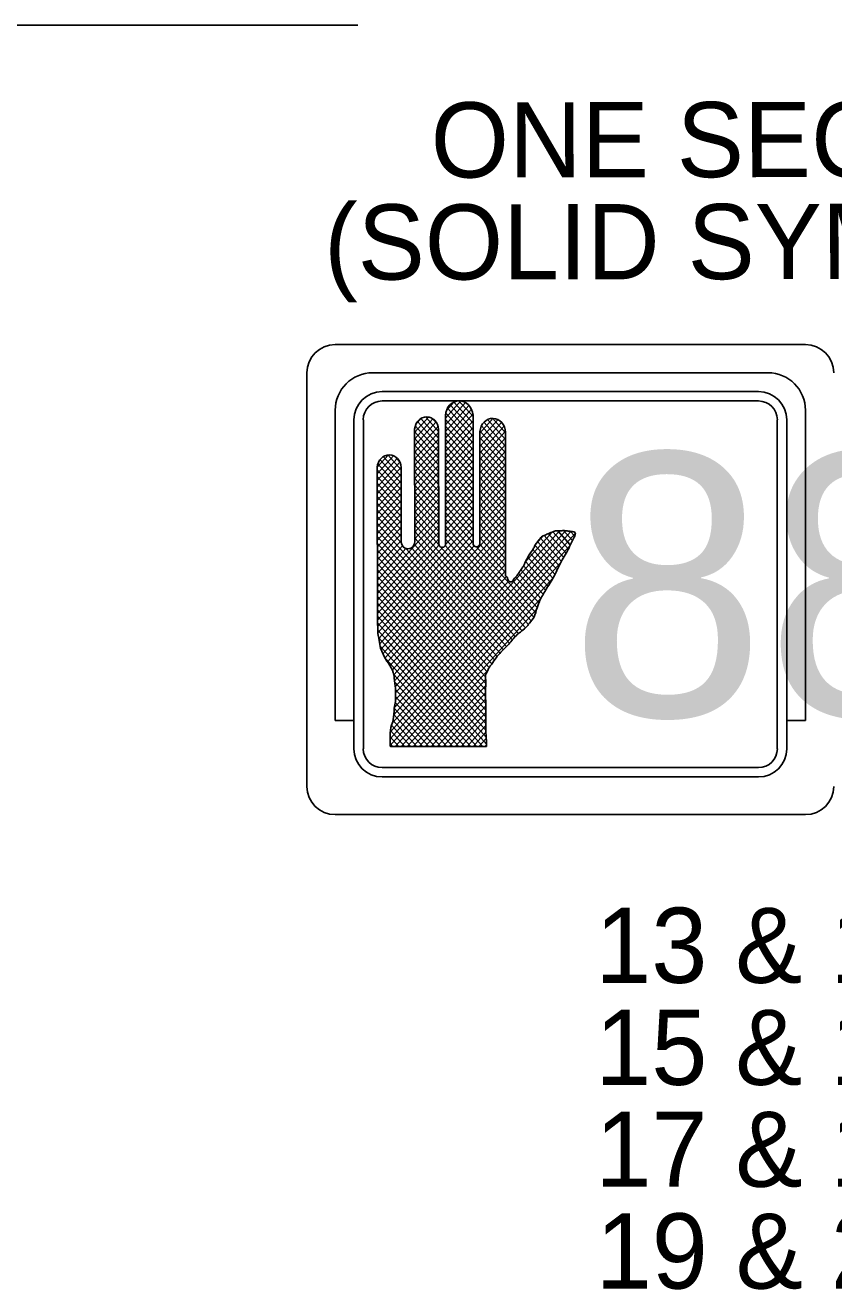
# Model space of a CAD drawing. Extents: x 1 to 35.4, y 0.4 to 10.6.
# Drawn here: x 4.903 to 5.619, y 9.065 to 10.185 of the extents above; entities that cross this region are included whole.
import ezdxf

# ---------------------------------------------------------------- set-up
doc = ezdxf.new("R2010")
doc.units = 0
doc.layers.add('T_Drafting', color=7, linetype='Continuous')
doc.layers.add('T_Notes', color=7, linetype='Continuous')

msp = doc.modelspace()

# ---------------------------------------------------------------- linework, layer by layer
at = {"layer": 'T_Drafting'}
for p, q in [((5.1772, 9.9023), (5.5938, 9.9023)), ((5.1522, 9.8773), (5.1522, 9.5106)), ((5.2105, 9.8773), (5.5605, 9.8773)), ((5.2188, 9.8606), (5.5522, 9.8606)), ((5.2188, 9.8523), (5.5522, 9.8523)), ((5.2749, 9.837), (5.2886, 9.8523)), ((5.2867, 9.8524), (5.2993, 9.8384)), ((5.1772, 9.844), (5.1772, 9.569)), ((5.2749, 9.8312), (5.2927, 9.8509)), ((5.2749, 9.8253), (5.2957, 9.8484)), ((5.2749, 9.8194), (5.298, 9.845)), ((5.2749, 9.8135), (5.2992, 9.8405)), ((5.2751, 9.8416), (5.2993, 9.8148)), ((5.2758, 9.8439), (5.2825, 9.8514)), ((5.2767, 9.8458), (5.2993, 9.8207)), ((5.2791, 9.849), (5.2993, 9.8266)), ((5.2823, 9.8513), (5.2993, 9.8325)), ((5.2945, 9.8496), (5.2968, 9.847)), ((5.5938, 9.569), (5.5938, 9.844)), ((5.1938, 9.8356), (5.1938, 9.544)), ((5.2022, 9.8356), (5.2022, 9.544)), ((5.2476, 9.8244), (5.2599, 9.838)), ((5.2476, 9.8185), (5.2637, 9.8364)), ((5.2476, 9.8126), (5.2666, 9.8337)), ((5.2476, 9.8067), (5.2684, 9.8298)), ((5.2482, 9.8303), (5.2688, 9.8074)), ((5.2485, 9.8313), (5.2537, 9.8371)), ((5.2501, 9.8341), (5.2688, 9.8133)), ((5.253, 9.8367), (5.2688, 9.8192)), ((5.2571, 9.8381), (5.2688, 9.8251)), ((5.2642, 9.8361), (5.267, 9.833)), ((5.275, 9.7256), (5.2749, 9.8394)), ((5.2749, 9.836), (5.2993, 9.8089)), ((5.2749, 9.8076), (5.2993, 9.8347)), ((5.2749, 9.8301), (5.2993, 9.803)), ((5.2993, 9.8397), (5.2994, 9.7268)), ((5.3054, 9.8238), (5.3172, 9.8369)), ((5.3054, 9.8179), (5.3214, 9.8357)), ((5.3054, 9.812), (5.3246, 9.8333)), ((5.3054, 9.8061), (5.3269, 9.83)), ((5.3067, 9.8302), (5.3281, 9.8064)), ((5.309, 9.8335), (5.3281, 9.8123)), ((5.3122, 9.8358), (5.3281, 9.8182)), ((5.3165, 9.8369), (5.3281, 9.8241)), ((5.5688, 9.544), (5.5688, 9.8356)), ((5.5772, 9.544), (5.5772, 9.8356)), ((5.2477, 9.7278), (5.2476, 9.8272)), ((5.2476, 9.8251), (5.2688, 9.8015)), ((5.2476, 9.8008), (5.2688, 9.8244)), ((5.2476, 9.8192), (5.2688, 9.7956)), ((5.2476, 9.795), (5.2688, 9.8185)), ((5.2688, 9.8269), (5.2689, 9.7262)), ((5.2749, 9.8017), (5.2993, 9.8288)), ((5.2749, 9.8242), (5.2993, 9.7971)), ((5.2749, 9.7958), (5.2993, 9.8229)), ((5.2749, 9.8183), (5.2993, 9.7912)), ((5.3054, 9.8257), (5.3281, 9.8005)), ((5.3055, 9.7262), (5.3054, 9.8254)), ((5.3054, 9.8003), (5.328, 9.8254)), ((5.3054, 9.8198), (5.3281, 9.7946)), ((5.3054, 9.7944), (5.3281, 9.8195)), ((5.3281, 9.8246), (5.3282, 9.697)), ((5.2476, 9.8133), (5.2688, 9.7897)), ((5.2476, 9.7891), (5.2688, 9.8126)), ((5.2476, 9.8074), (5.2689, 9.7838)), ((5.2476, 9.7832), (5.2688, 9.8067)), ((5.2749, 9.79), (5.2993, 9.817)), ((5.2749, 9.8124), (5.2993, 9.7853)), ((5.275, 9.7841), (5.2993, 9.8111)), ((5.3054, 9.8139), (5.3281, 9.7887)), ((5.3054, 9.7885), (5.3281, 9.8137)), ((5.3054, 9.808), (5.3281, 9.7828)), ((5.3054, 9.7826), (5.3281, 9.8078)), ((5.2145, 9.7935), (5.2244, 9.8045)), ((5.2145, 9.7876), (5.229, 9.8037)), ((5.2145, 9.7817), (5.2322, 9.8014)), ((5.2145, 9.7758), (5.2345, 9.7981)), ((5.215, 9.7965), (5.2357, 9.7735)), ((5.2169, 9.8003), (5.2357, 9.7794)), ((5.2198, 9.803), (5.2357, 9.7853)), ((5.2238, 9.8044), (5.2357, 9.7912)), ((5.2305, 9.8029), (5.2342, 9.7987)), ((5.2476, 9.8015), (5.2689, 9.7779)), ((5.2476, 9.7773), (5.2688, 9.8009)), ((5.2476, 9.7956), (5.2689, 9.772)), ((5.2749, 9.8065), (5.2993, 9.7794)), ((5.2749, 9.8006), (5.2994, 9.7735)), ((5.275, 9.7782), (5.2993, 9.8053)), ((5.275, 9.7723), (5.2993, 9.7994)), ((5.3054, 9.8021), (5.3281, 9.7769)), ((5.3054, 9.7962), (5.3281, 9.771)), ((5.3055, 9.7767), (5.3281, 9.8019)), ((5.3055, 9.7708), (5.3281, 9.796)), ((5.2146, 9.6561), (5.2144, 9.7935)), ((5.2145, 9.7699), (5.2357, 9.7935)), ((5.2145, 9.7912), (5.2357, 9.7676)), ((5.2145, 9.764), (5.2357, 9.7876)), ((5.2145, 9.7853), (5.2357, 9.7617)), ((5.2357, 9.7933), (5.2357, 9.7277)), ((5.2476, 9.7897), (5.2689, 9.7661)), ((5.2476, 9.7714), (5.2688, 9.795)), ((5.2477, 9.7655), (5.2688, 9.7891)), ((5.2749, 9.7947), (5.2994, 9.7676)), ((5.2749, 9.7888), (5.2994, 9.7617)), ((5.275, 9.7664), (5.2993, 9.7935)), ((5.275, 9.7605), (5.2993, 9.7876)), ((5.3054, 9.7903), (5.3281, 9.7651)), ((5.3054, 9.7844), (5.3281, 9.7592)), ((5.3055, 9.7649), (5.3281, 9.7901)), ((5.3055, 9.7591), (5.3281, 9.7842)), ((5.2145, 9.7581), (5.2357, 9.7817)), ((5.2145, 9.7794), (5.2357, 9.7558)), ((5.2145, 9.7523), (5.2357, 9.7758)), ((5.2145, 9.7735), (5.2357, 9.7499)), ((5.2476, 9.7838), (5.2689, 9.7602)), ((5.2476, 9.7779), (5.2689, 9.7543)), ((5.2477, 9.7596), (5.2689, 9.7832)), ((5.2477, 9.7538), (5.2689, 9.7773)), ((5.275, 9.7829), (5.2994, 9.7558)), ((5.275, 9.7547), (5.2993, 9.7817)), ((5.275, 9.777), (5.2994, 9.7499)), ((5.275, 9.7488), (5.2994, 9.7758)), ((5.3054, 9.7785), (5.3282, 9.7533)), ((5.3055, 9.7532), (5.3281, 9.7783)), ((5.2145, 9.7464), (5.2357, 9.7699)), ((5.2145, 9.7676), (5.2357, 9.744)), ((5.2145, 9.7405), (5.2357, 9.764)), ((5.2476, 9.772), (5.2689, 9.7484)), ((5.2477, 9.7479), (5.2689, 9.7714)), ((5.2477, 9.7661), (5.2689, 9.7425)), ((5.2477, 9.742), (5.2689, 9.7655)), ((5.275, 9.7711), (5.2994, 9.744)), ((5.275, 9.7429), (5.2994, 9.7699)), ((5.275, 9.7652), (5.2994, 9.7381)), ((5.275, 9.737), (5.2994, 9.7641)), ((5.3055, 9.7726), (5.3282, 9.7474)), ((5.3055, 9.7473), (5.3281, 9.7725)), ((5.3055, 9.7667), (5.3282, 9.7415)), ((5.3055, 9.7414), (5.3281, 9.7666)), ((5.2145, 9.7617), (5.2357, 9.7381)), ((5.2145, 9.7346), (5.2357, 9.7582)), ((5.2145, 9.7558), (5.2357, 9.7322)), ((5.2145, 9.7287), (5.2357, 9.7523)), ((5.2477, 9.7602), (5.2689, 9.7366)), ((5.2477, 9.7361), (5.2689, 9.7597)), ((5.2477, 9.7543), (5.2689, 9.7307)), ((5.2477, 9.7302), (5.2689, 9.7538)), ((5.275, 9.7593), (5.2994, 9.7322)), ((5.275, 9.7311), (5.2994, 9.7582)), ((5.275, 9.7534), (5.2993, 9.7264)), ((5.275, 9.7252), (5.2994, 9.7523)), ((5.3055, 9.7608), (5.3282, 9.7356)), ((5.3055, 9.7355), (5.3281, 9.7607)), ((5.3055, 9.7549), (5.3282, 9.7297)), ((5.3055, 9.7296), (5.3282, 9.7548)), ((5.2145, 9.7499), (5.2359, 9.7261)), ((5.2145, 9.7228), (5.2357, 9.7464)), ((5.2145, 9.744), (5.3208, 9.6259)), ((5.2145, 9.7169), (5.2357, 9.7405)), ((5.2146, 9.6875), (5.2689, 9.7479)), ((5.2146, 9.6816), (5.2689, 9.742)), ((5.2148, 9.6524), (5.2994, 9.7464)), ((5.215, 9.6467), (5.2994, 9.7405)), ((5.2195, 9.6282), (5.3282, 9.7489)), ((5.2215, 9.6246), (5.3282, 9.743)), ((5.2477, 9.7484), (5.2692, 9.7245)), ((5.2477, 9.7425), (5.3368, 9.6435)), ((5.275, 9.7475), (5.3532, 9.6606)), ((5.275, 9.7416), (5.3509, 9.6573)), ((5.3055, 9.749), (5.3282, 9.7238)), ((5.3055, 9.7431), (5.3282, 9.7179)), ((5.2145, 9.7381), (5.3183, 9.6227)), ((5.2145, 9.7111), (5.2357, 9.7346)), ((5.2145, 9.7322), (5.3161, 9.6193)), ((5.2145, 9.7052), (5.2357, 9.7287)), ((5.2146, 9.6757), (5.2689, 9.7361)), ((5.2146, 9.6699), (5.2689, 9.7302)), ((5.2158, 9.6418), (5.2994, 9.7346)), ((5.2166, 9.6368), (5.2994, 9.7287)), ((5.2236, 9.621), (5.3282, 9.7371)), ((5.2257, 9.6174), (5.3282, 9.7313)), ((5.2259, 9.5528), (5.39, 9.7351)), ((5.226, 9.5588), (5.3861, 9.7367)), ((5.2278, 9.5667), (5.3813, 9.7373)), ((5.229, 9.5739), (5.376, 9.7373)), ((5.2477, 9.7366), (5.3342, 9.6405)), ((5.2477, 9.7307), (5.3316, 9.6375)), ((5.275, 9.7357), (5.3484, 9.6542)), ((5.275, 9.7298), (5.3458, 9.6512)), ((5.3055, 9.7372), (5.3282, 9.712)), ((5.3055, 9.7313), (5.3282, 9.7061)), ((5.3455, 9.7093), (5.3698, 9.7362)), ((5.3555, 9.7263), (5.3612, 9.7326)), ((5.359, 9.7308), (5.3776, 9.7101)), ((5.3623, 9.733), (5.3796, 9.7138)), ((5.366, 9.7348), (5.3818, 9.7173)), ((5.3699, 9.7363), (5.3838, 9.7209)), ((5.3744, 9.7373), (5.3855, 9.7249)), ((5.3797, 9.7373), (5.3874, 9.7287)), ((5.3854, 9.7368), (5.3892, 9.7326)), ((5.2145, 9.7263), (5.3137, 9.6161)), ((5.2145, 9.7204), (5.3118, 9.6123)), ((5.2146, 9.664), (5.2691, 9.7246)), ((5.2146, 9.6993), (5.2368, 9.724)), ((5.2146, 9.6581), (5.2726, 9.7226)), ((5.2146, 9.6934), (5.2398, 9.7215)), ((5.2177, 9.6321), (5.3004, 9.7239)), ((5.2259, 9.5469), (5.3849, 9.7235)), ((5.2277, 9.6137), (5.3282, 9.7254)), ((5.2293, 9.6096), (5.3282, 9.7195)), ((5.2402, 9.7213), (5.3235, 9.6288)), ((5.2448, 9.7221), (5.3262, 9.6317)), ((5.2473, 9.7253), (5.3289, 9.6346)), ((5.2707, 9.7228), (5.3396, 9.6462)), ((5.2747, 9.7243), (5.3428, 9.6486)), ((5.3023, 9.7231), (5.3548, 9.6647)), ((5.3054, 9.7255), (5.3282, 9.7002)), ((5.3499, 9.7173), (5.3699, 9.6951)), ((5.3523, 9.7206), (5.3719, 9.6988)), ((5.3543, 9.7242), (5.3738, 9.7025)), ((5.3565, 9.7277), (5.3757, 9.7063)), ((5.2145, 9.7145), (5.3105, 9.6079)), ((5.2145, 9.7086), (5.3106, 9.6018)), ((5.2299, 9.6043), (5.3282, 9.7136)), ((5.2303, 9.5459), (5.3769, 9.7088)), ((5.2304, 9.599), (5.3282, 9.7077)), ((5.3441, 9.7061), (5.3635, 9.6845)), ((5.3459, 9.71), (5.3657, 9.688)), ((5.3479, 9.7137), (5.3679, 9.6914)), ((5.2146, 9.7027), (5.3104, 9.5962)), ((5.2146, 9.6968), (5.3104, 9.5903)), ((5.2306, 9.5875), (5.329, 9.6968)), ((5.2307, 9.5935), (5.3282, 9.7018)), ((5.2356, 9.5459), (5.37, 9.6952)), ((5.3371, 9.6962), (5.3577, 9.6733)), ((5.3396, 9.6993), (5.3595, 9.6772)), ((5.3418, 9.7027), (5.3615, 9.6809)), ((5.2146, 9.6909), (5.3107, 9.5841)), ((5.2146, 9.685), (5.3107, 9.5782)), ((5.2297, 9.5806), (5.3309, 9.693)), ((5.3346, 9.693), (5.3561, 9.6691)), ((5.2146, 9.6791), (5.3107, 9.5723)), ((5.2146, 9.6732), (5.3107, 9.5664)), ((5.2409, 9.5459), (5.3603, 9.6785)), ((5.2146, 9.6673), (5.3108, 9.5605)), ((5.2146, 9.6614), (5.311, 9.5543)), ((5.2462, 9.5459), (5.3555, 9.6674)), ((5.2146, 9.6555), (5.3113, 9.548)), ((5.2148, 9.6494), (5.3079, 9.546)), ((5.2157, 9.6425), (5.3026, 9.546)), ((5.2169, 9.6353), (5.2973, 9.546)), ((5.2221, 9.6237), (5.292, 9.546)), ((5.2292, 9.6098), (5.2867, 9.546)), ((5.2515, 9.5459), (5.3127, 9.6139)), ((5.2568, 9.5459), (5.3106, 9.6056)), ((5.23, 9.603), (5.2814, 9.546)), ((5.2305, 9.5966), (5.2761, 9.546)), ((5.2621, 9.5459), (5.3105, 9.5997)), ((5.2304, 9.5849), (5.2655, 9.5459)), ((5.2307, 9.5904), (5.2708, 9.5459)), ((5.2675, 9.5459), (5.3104, 9.5936)), ((5.2728, 9.5459), (5.3105, 9.5879)), ((5.229, 9.5747), (5.2549, 9.5459)), ((5.2296, 9.5799), (5.2602, 9.5459)), ((5.2781, 9.546), (5.3107, 9.5822)), ((5.2834, 9.546), (5.3107, 9.5763)), ((5.1772, 9.569), (5.1938, 9.569)), ((5.2261, 9.5602), (5.239, 9.5459)), ((5.2272, 9.5649), (5.2443, 9.5459)), ((5.2284, 9.5694), (5.2496, 9.5459)), ((5.2887, 9.546), (5.3107, 9.5704)), ((5.294, 9.546), (5.3107, 9.5645)), ((5.5772, 9.569), (5.5938, 9.569)), ((5.2259, 9.5546), (5.2337, 9.5459)), ((5.2993, 9.546), (5.3108, 9.5587)), ((5.3046, 9.546), (5.311, 9.5531)), ((5.2259, 9.5487), (5.2284, 9.5459)), ((5.2263, 9.5459), (5.2259, 9.5464)), ((5.311, 9.546), (5.2263, 9.5459)), ((5.3099, 9.546), (5.3113, 9.5475)), ((5.3113, 9.5459), (5.311, 9.546)), ((5.2188, 9.5273), (5.5522, 9.5273)), ((5.2188, 9.519), (5.5522, 9.519)), ((5.1772, 9.4856), (5.5938, 9.4856))]:
    msp.add_line(p, q, dxfattribs=at)
for centre, radius, start, end in [((5.1772, 9.8773), 0.025, 90, 180), ((5.5938, 9.8773), 0.025, 0, 90), ((5.2105, 9.844), 0.0333, 90, 180), ((5.5605, 9.844), 0.0333, 0, 90), ((5.2188, 9.8356), 0.025, 90, 180), ((5.2188, 9.8356), 0.0167, 90, 180), ((5.5522, 9.8356), 0.025, 0, 90), ((5.5522, 9.8356), 0.0167, 0, 90), ((5.2188, 9.544), 0.025, 180, 270), ((5.2188, 9.544), 0.0167, 180, 270), ((5.5522, 9.544), 0.025, 270, 0), ((5.5522, 9.544), 0.0167, 270, 0), ((5.1772, 9.5106), 0.025, 180, 270), ((5.5938, 9.5106), 0.025, 270, 0)]:
    msp.add_arc(centre, radius, start, end, dxfattribs=at)
for centre, major_axis, start_param, end_param in [((5.2871, 9.8388), (0, -0.0136), 1.640121, 4.665593), ((5.2582, 9.8264), (0, -0.0118), 1.618611, 4.644084), ((5.3167, 9.8242), (0, -0.0126), 1.597842, 4.623315), ((5.2251, 9.7927), (0, -0.0118), 1.618611, 4.644084), ((5.2417, 9.7278), (0, -0.00664), 4.713646, 7.855239), ((5.272, 9.7259), (0, -0.0034), 4.633755, 7.775348), ((5.3024, 9.7265), (0, -0.00345), 4.624552, 7.766145)]:
    msp.add_ellipse(centre, major_axis=major_axis, ratio=0.9, start_param=start_param, end_param=end_param, dxfattribs=at)
for points in [[(5.3282, 9.697), (5.3291, 9.6967), (5.3302, 9.6942), (5.3317, 9.6922), (5.3326, 9.6919), (5.334, 9.6922), (5.3349, 9.6935), (5.3376, 9.6968), (5.3396, 9.6994), (5.3408, 9.7013), (5.3419, 9.703), (5.344, 9.7059), (5.3452, 9.7085), (5.3469, 9.7121), (5.3481, 9.7141), (5.3501, 9.7176), (5.3525, 9.7209), (5.3542, 9.7242), (5.3563, 9.7274), (5.3581, 9.7297), (5.3607, 9.7323), (5.3639, 9.7336), (5.3657, 9.7346), (5.3683, 9.7356), (5.3706, 9.7366), (5.3742, 9.7373), (5.3771, 9.7373), (5.3809, 9.7373), (5.3844, 9.7369), (5.3885, 9.7363), (5.3897, 9.7356), (5.39, 9.7347), (5.3882, 9.7304), (5.3871, 9.7281), (5.3859, 9.7258), (5.3847, 9.7232), (5.3841, 9.7216), (5.3818, 9.7173), (5.3783, 9.7115), (5.3736, 9.702), (5.3678, 9.6912), (5.3631, 9.6837), (5.3604, 9.6789), (5.3581, 9.6743), (5.3567, 9.6706), (5.356, 9.6688), (5.3534, 9.6609), (5.3493, 9.6554), (5.3461, 9.6515), (5.3414, 9.6475), (5.3385, 9.6452), (5.3309, 9.6367), (5.3241, 9.6296), (5.3198, 9.6247), (5.3159, 9.6191), (5.314, 9.6167), (5.3124, 9.6133), (5.3107, 9.61), (5.3107, 9.6028), (5.3104, 9.5964), (5.3104, 9.5905), (5.3107, 9.5827), (5.3107, 9.5752), (5.3107, 9.5631), (5.311, 9.5534), (5.3113, 9.5498), (5.3113, 9.5472), (5.3113, 9.5459)], [(5.2259, 9.5464), (5.2259, 9.5516), (5.2261, 9.5604), (5.2285, 9.5696), (5.2296, 9.58), (5.2305, 9.5859), (5.2305, 9.5973), (5.2296, 9.6067), (5.2287, 9.6116), (5.2243, 9.6198), (5.2196, 9.6279), (5.217, 9.6348), (5.2158, 9.6419), (5.2149, 9.6475), (5.2149, 9.651), (5.2146, 9.6561)]]:
    msp.add_spline(points, degree=3, dxfattribs=at)
at = {"layer": 'T_Notes'}
msp.add_line((3.5609, 10.1853), (5.1973, 10.1853), dxfattribs=at)

# ---------------------------------------------------------------- texts
at = {"layer": 'T_Drafting'}
for s, height, p in [('ONE SECTION', 0.066667, (5.2619, 10.0503)), ('(SOLID SYMBOL)', 0.066667, (5.1675, 9.9598)), ('88', 0.23333, (5.3849, 9.5727))]:
    msp.add_text(s, height=height, rotation=0.072, dxfattribs=at).set_placement(p)
at = {"layer": 'T_Notes'}
for s, p in [('13 & 14', (5.4077, 9.3365)), ('15 & 16', (5.4077, 9.2461)), ('17 & 18', (5.4078, 9.1558)), ('19 & 20', (5.4081, 9.0655))]:
    msp.add_text(s, height=0.06667, dxfattribs=at).set_placement(p)

doc.saveas('drawing.dxf')
